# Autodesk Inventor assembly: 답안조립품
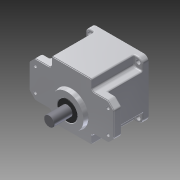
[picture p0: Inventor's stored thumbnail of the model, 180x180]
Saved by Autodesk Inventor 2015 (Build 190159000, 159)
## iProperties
Created: 2016-02
Part Number: 답안조립품
Document SubType Name: Assembly
Designer: Administrator
Author: Administrator
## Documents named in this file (10)
- C:\Users\Administrator\Desktop\460209V1011\답안조립품.iam
- C:\Users\Administrator\Desktop\460209V1011\본체.ipt
- C:\Users\Administrator\Desktop\460209V1011\커버.ipt
- C:\Users\Administrator\Desktop\460209V1011\베어링 608.ipt
- C:\Users\Administrator\Desktop\460209V1011\오일실 8 22 7.ipt
- C:\Users\Administrator\Desktop\460209V1011\오일실 17 32 8.ipt
- C:\Users\Administrator\Desktop\460209V1011\볼트 M4 x 10.ipt
- C:\Users\Administrator\Desktop\460209V1011\베어링 6003.ipt
- C:\Users\Administrator\Desktop\460209V1011\메인축.ipt
- C:\Users\Administrator\Desktop\460209V1011\서브축.ipt
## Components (2 placed, 1 different names)
1. ISO 4762 M4 x 10:1 — Insert:1
2. ISO 4762 M4 x 10:2 — Insert:2
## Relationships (2: Insert 2)
- Insert:1: ISO 4762 M4 x 10:1
- Insert:2: ISO 4762 M4 x 10:2
